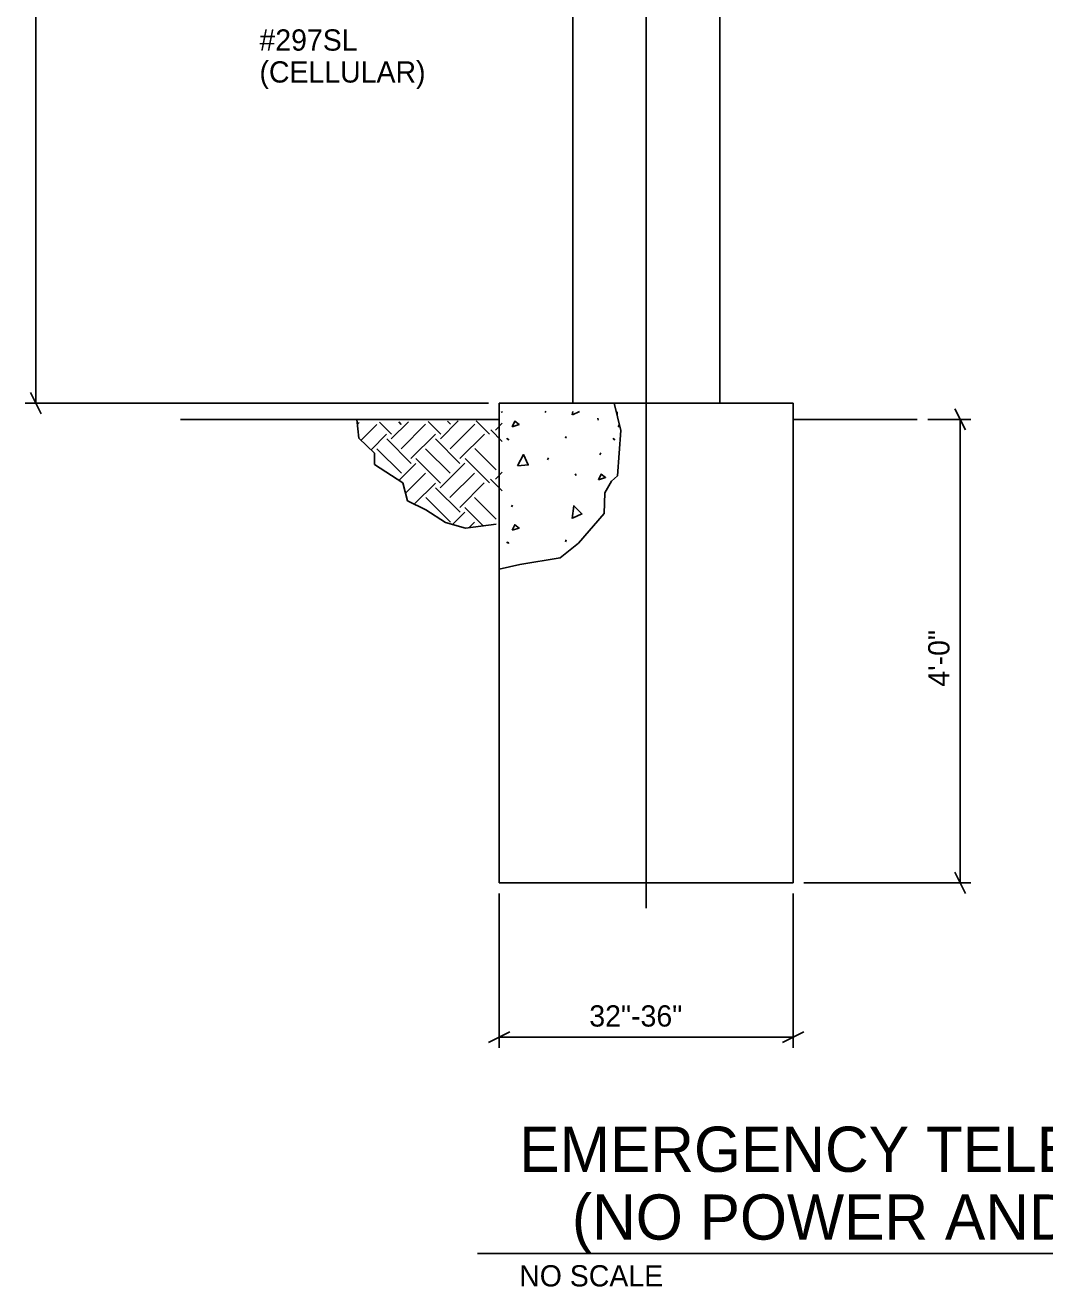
# Model space of a CAD drawing. Extents: x 10097.7 to 10174.5, y 10050.6 to 10139.4.
# Drawn here: x 10098.39 to 10130.32, y 10051.82 to 10091.35 of the extents above; entities that cross this region are included whole.
import ezdxf

# ---------------------------------------------------------------- set-up
doc = ezdxf.new("R2010")
doc.units = 0
for name, color, linetype in [('Level 52', 7, 'Continuous'), ('Level 57', 7, 'Continuous'), ('Level 60', 7, 'Continuous'), ('Level 61', 7, 'Continuous'), ('Level 63', 7, 'Continuous')]:
    doc.layers.add(name, color=color, linetype=linetype)

msp = doc.modelspace()

# ---------------------------------------------------------------- linework, layer by layer
at = {"layer": 'Level 52'}
msp.add_line((10112.55, 10052.864), (10158.777, 10052.864), dxfattribs=at)
at = {"layer": 'Level 57'}
for p, q in [((10098.721, 10079.512), (10098.721, 10110.189)), ((10098.888, 10079.178), (10098.555, 10079.845)), ((10112.903, 10079.512), (10098.388, 10079.512)), ((10127.504, 10079.335), (10127.837, 10078.668)), ((10126.656, 10079.001), (10128.004, 10079.001)), ((10127.67, 10079.001), (10127.67, 10064.476)), ((10127.837, 10064.143), (10127.504, 10064.809)), ((10113.236, 10064.143), (10113.236, 10059.306)), ((10122.444, 10064.143), (10122.444, 10059.306)), ((10122.778, 10064.476), (10128.004, 10064.476)), ((10112.903, 10059.473), (10113.569, 10059.806)), ((10122.778, 10059.806), (10122.111, 10059.473)), ((10113.236, 10059.64), (10122.444, 10059.64))]:
    msp.add_line(p, q, dxfattribs=at)
at = {"layer": 'Level 60'}
for p, q in [((10113.305, 10079.243), (10113.329, 10079.219)), ((10114.676, 10079.211), (10114.696, 10079.255)), ((10117.046, 10078.649), (10116.839, 10079.512)), ((10116.93, 10079.13), (10116.93, 10079.234)), ((10108.778, 10079.001), (10108.841, 10078.409)), ((10108.794, 10078.852), (10108.843, 10078.901)), ((10108.905, 10078.348), (10109.399, 10078.843)), ((10109.484, 10078.911), (10109.86, 10078.535)), ((10109.854, 10078.387), (10110.392, 10078.925)), ((10110.089, 10078.92), (10110.167, 10078.843)), ((10110.162, 10078.08), (10110.929, 10078.848)), ((10111.007, 10078.935), (10111.401, 10078.541)), ((10111.39, 10078.387), (10111.953, 10078.95)), ((10111.612, 10078.944), (10111.708, 10078.848)), ((10111.697, 10078.08), (10112.465, 10078.848)), ((10112.508, 10078.958), (10112.926, 10078.541)), ((10113.113, 10078.667), (10113.329, 10078.884)), ((10116.326, 10079.037), (10116.333, 10078.975)), ((10108.841, 10078.409), (10109.332, 10077.944)), ((10109.22, 10078.049), (10109.706, 10078.535)), ((10109.712, 10078.387), (10110.48, 10077.62)), ((10110.469, 10077.773), (10111.236, 10078.541)), ((10111.236, 10078.387), (10112.004, 10077.619)), ((10112.004, 10077.773), (10112.772, 10078.541)), ((10112.97, 10078.668), (10113.329, 10078.309)), ((10113.476, 10078.407), (10113.504, 10078.365)), ((10113.504, 10078.391), (10113.531, 10078.349)), ((10115.308, 10078.407), (10115.335, 10078.469)), ((10116.799, 10078.407), (10116.827, 10078.365)), ((10116.827, 10078.391), (10116.855, 10078.349)), ((10117.046, 10078.649), (10116.941, 10077.233)), ((10109.405, 10078.08), (10110.173, 10077.313)), ((10110.929, 10078.08), (10111.697, 10077.312)), ((10112.471, 10078.086), (10113.137, 10077.42)), ((10109.332, 10077.944), (10109.332, 10077.582)), ((10109.332, 10077.582), (10110.21, 10077.013)), ((10110.092, 10077.089), (10110.622, 10077.619)), ((10110.622, 10077.773), (10111.39, 10077.005)), ((10111.385, 10076.857), (10112.152, 10077.625)), ((10112.164, 10077.779), (10112.931, 10077.011)), ((10114.746, 10077.733), (10114.773, 10077.795)), ((10116.39, 10077.892), (10116.418, 10077.955)), ((10110.3, 10076.683), (10110.929, 10077.312)), ((10111.692, 10076.55), (10112.46, 10077.318)), ((10113.113, 10077.132), (10113.329, 10077.348)), ((10115.613, 10077.289), (10115.641, 10077.247)), ((10116.749, 10077.063), (10116.941, 10077.233)), ((10110.21, 10077.013), (10110.365, 10076.445)), ((10110.572, 10076.341), (10111.236, 10077.005)), ((10111.242, 10076.857), (10112.01, 10076.09)), ((10111.999, 10076.243), (10112.767, 10077.011)), ((10112.959, 10077.132), (10113.329, 10076.762)), ((10116.543, 10076.701), (10116.749, 10077.063)), ((10110.365, 10076.445), (10110.933, 10076.161)), ((10110.935, 10076.55), (10111.703, 10075.782)), ((10112.46, 10076.55), (10113.137, 10075.873)), ((10116.517, 10076.055), (10116.543, 10076.701)), ((10110.933, 10076.161), (10111.553, 10075.773)), ((10111.772, 10075.709), (10112.152, 10076.089)), ((10112.152, 10076.243), (10112.729, 10075.667)), ((10113.622, 10076.255), (10113.649, 10076.317)), ((10115.716, 10075.124), (10116.517, 10076.055)), ((10111.553, 10075.773), (10112.173, 10075.592)), ((10112.173, 10075.592), (10113.137, 10075.721)), ((10112.284, 10075.607), (10112.46, 10075.782)), ((10115.308, 10075.166), (10115.335, 10075.228)), ((10113.476, 10075.166), (10113.504, 10075.124)), ((10113.504, 10075.15), (10113.531, 10075.108)), ((10115.148, 10074.659), (10115.716, 10075.124)), ((10113.236, 10074.305), (10113.882, 10074.453)), ((10113.882, 10074.453), (10115.148, 10074.659))]:
    msp.add_line(p, q, dxfattribs=at)
for points in [[(10115.52, 10079.14), (10115.535, 10079.247)], [(10115.749, 10079.245), (10115.527, 10079.142)], [(10113.636, 10078.767), (10113.719, 10078.941), (10113.858, 10078.837), (10113.636, 10078.767)], [(10116.959, 10078.767), (10116.998, 10078.849)], [(10117.013, 10078.784), (10116.959, 10078.767)], [(10113.809, 10077.545), (10113.996, 10077.899), (10114.142, 10077.573), (10113.816, 10077.545)], [(10116.341, 10077.108), (10116.424, 10077.282), (10116.563, 10077.178), (10116.341, 10077.108)], [(10115.52, 10075.899), (10115.575, 10076.295), (10115.824, 10076.039), (10115.527, 10075.901)], [(10113.636, 10075.527), (10113.719, 10075.7), (10113.858, 10075.596), (10113.636, 10075.527)]]:
    msp.add_lwpolyline(points, dxfattribs=at)
at = {"layer": 'Level 61'}
for p, q in [((10117.84, 10063.682), (10117.84, 10111.993)), ((10115.538, 10079.512), (10115.538, 10110.189)), ((10120.142, 10079.512), (10120.142, 10110.189)), ((10113.236, 10079.512), (10113.236, 10064.476)), ((10113.236, 10079.512), (10122.444, 10079.512)), ((10122.444, 10079.512), (10122.444, 10064.476)), ((10103.246, 10079.001), (10113.236, 10079.001)), ((10122.444, 10079.001), (10126.323, 10079.001)), ((10113.236, 10064.476), (10122.444, 10064.476))]:
    msp.add_line(p, q, dxfattribs=at)

# ---------------------------------------------------------------- texts
at = {"layer": 'Level 52'}
for s, height, p in [('EMERGENCY TELEPHONE FREE STANDING', 1.41667, (10113.86, 10055.421)), ('(NO POWER AND TELEPHONE NEARBY)', 1.41667, (10115.512, 10053.296)), ('NO SCALE', 0.6667, (10113.86, 10051.829))]:
    msp.add_text(s, height=height, dxfattribs=at).set_placement(p)
at = {"layer": 'Level 57'}
msp.add_text('4\'-0"', height=0.6667, rotation=90, dxfattribs=at).set_placement((10127.337, 10070.625))
msp.add_text('32"-36"', height=0.6667, dxfattribs=at).set_placement((10116.055, 10059.973))
at = {"layer": 'Level 63'}
for s, p in [('#297SL', (10105.724, 10090.555)), ('(CELLULAR)', (10105.724, 10089.555))]:
    msp.add_text(s, height=0.6667, dxfattribs=at).set_placement(p)

doc.saveas('drawing.dxf')
